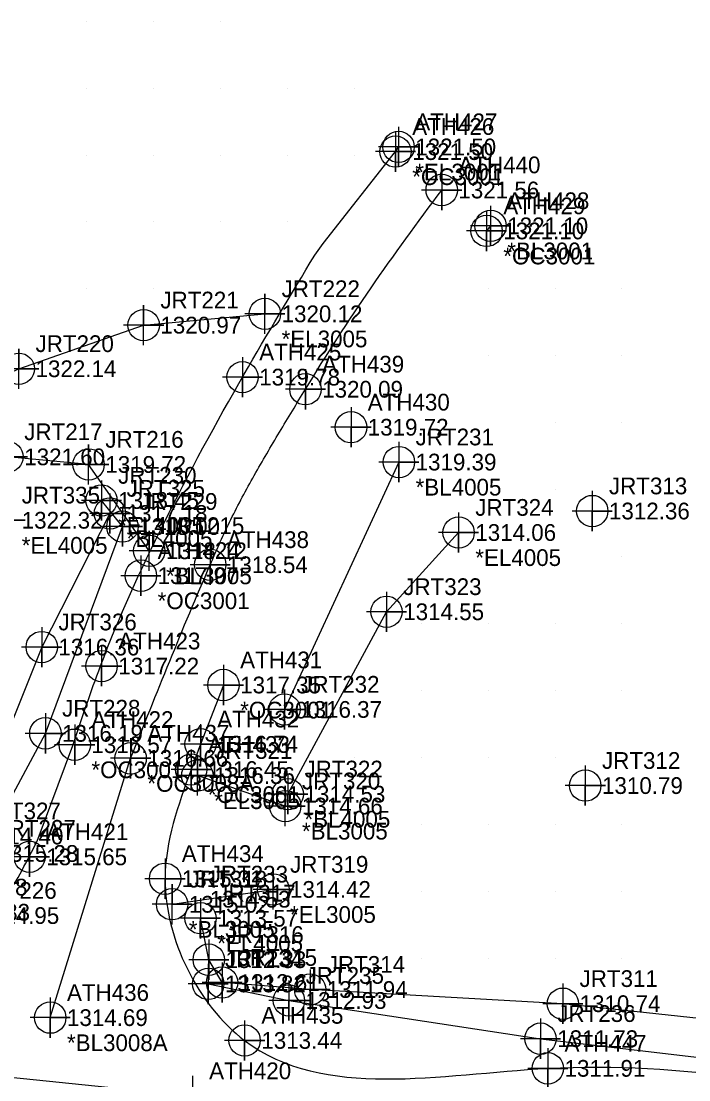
# Model space of a CAD drawing. Extents: x 1234484 to 1235382, y 695050 to 695510.
# Drawn here: x 1234580.2 to 1234680, y 695351.8 to 695510 of the extents above; entities that cross this region are included whole.
import ezdxf

# ---------------------------------------------------------------- set-up
doc = ezdxf.new("R2010")
doc.units = 0
for name, color, linetype in [('Exist DTM Breakline', 7, 'Continuous'), ('Exist DTM Breakline Cogo Comment', 7, 'Continuous'), ('Exist DTM Breakline Cogo Elevation', 7, 'Continuous'), ('Exist DTM Breakline Cogo Number', 7, 'Continuous'), ('Exist DTM Breakline Cogo Point CELL', 7, 'Continuous'), ('Exist DTM Crownline', 7, 'Continuous'), ('Exist DTM Crownline Cogo Comment', 7, 'Continuous'), ('Exist DTM Crownline Cogo Elevation', 7, 'Continuous'), ('Exist DTM Crownline Cogo Number', 7, 'Continuous'), ('Exist DTM Crownline Cogo Point CELL', 7, 'Continuous'), ('Exist DTM QL2 LIDAR Elevation Point', 7, 'Continuous'), ('Exist DTM Regular Point CELL', 7, 'Continuous'), ('Exist DTM Regular Point Cogo Elevation', 7, 'Continuous'), ('Exist DTM Regular Point Cogo Number', 7, 'Continuous'), ('Exist Roads EOP', 7, 'Continuous'), ('Exist Roads EOP Cogo Comment', 7, 'Continuous'), ('Exist Roads EOP Cogo Elevation', 7, 'Continuous'), ('Exist Roads EOP Cogo Number', 7, 'Continuous'), ('Exist Roads EOP Cogo Point CELL', 7, 'Continuous'), ('Exist Roads Soil', 7, 'Continuous'), ('Exist Roads Soil Cogo Comment', 7, 'Continuous'), ('Exist Roads Soil Cogo Elevation', 7, 'Continuous'), ('Exist Roads Soil Cogo Number', 7, 'Continuous'), ('Exist Roads Soil Cogo Point CELL', 7, 'Continuous')]:
    doc.layers.add(name, color=color, linetype=linetype)

msp = doc.modelspace()

# ---------------------------------------------------------------- linework, layer by layer
at = {"layer": 'Exist DTM Breakline'}
for points in [[(1234636.655, 695444.117), (1234619.55, 695407.153)], [(1234512.96, 695371.423), (1234547.569, 695368.537), (1234564.304, 695370.629), (1234571.291, 695376.351), (1234574.148, 695385.63), (1234583.803, 695403.581), (1234595.326, 695434.478), (1234592.189, 695438.384)], [(1234593.455, 695436.439), (1234583.26, 695416.47), (1234571.92, 695388.234), (1234566.927, 695376.85), (1234557.842, 695374.246), (1234516.908, 695379.248)], [(1234620.043, 695394.492), (1234634.807, 695421.746), (1234645.575, 695433.589)], [(1234866.911, 695345.376), (1234823.763, 695348.478), (1234767.785, 695355.619), (1234719.498, 695356.897), (1234661.167, 695363.182), (1234623.376, 695365.3), (1234610.221, 695366.341), (1234608.231, 695369.759), (1234607.001, 695375.947)], [(1234608.156, 695366.132), (1234620.219, 695363.657), (1234657.83, 695357.954), (1234716.822, 695351.015), (1234771.134, 695347.284), (1234823.515, 695343.018), (1234867.598, 695341.251), (1234907.686, 695335.753), (1234932.171, 695332.602)]]:
    msp.add_lwpolyline(points, dxfattribs=at)
at = {"layer": 'Exist DTM Breakline Cogo Point CELL'}
for points in [[(1234636.655, 695447.117), (1234636.655, 695441.117), (1234636.655, 695444.117), (1234639.655, 695444.117), (1234633.655, 695444.117)], [(1234592.189, 695441.384), (1234592.189, 695435.384), (1234592.189, 695438.384), (1234595.189, 695438.384), (1234589.189, 695438.384)], [(1234577.768, 695438.42), (1234577.768, 695432.42), (1234577.768, 695435.42), (1234580.768, 695435.42), (1234574.768, 695435.42)], [(1234593.455, 695439.439), (1234593.455, 695433.439), (1234593.455, 695436.439), (1234596.455, 695436.439), (1234590.455, 695436.439)], [(1234595.326, 695437.478), (1234595.326, 695431.478), (1234595.326, 695434.478), (1234598.326, 695434.478), (1234592.326, 695434.478)], [(1234645.575, 695436.589), (1234645.575, 695430.589), (1234645.575, 695433.589), (1234648.575, 695433.589), (1234642.575, 695433.589)], [(1234634.807, 695424.746), (1234634.807, 695418.746), (1234634.807, 695421.746), (1234637.807, 695421.746), (1234631.807, 695421.746)], [(1234583.26, 695419.47), (1234583.26, 695413.47), (1234583.26, 695416.47), (1234586.26, 695416.47), (1234580.26, 695416.47)], [(1234619.55, 695410.153), (1234619.55, 695404.153), (1234619.55, 695407.153), (1234622.55, 695407.153), (1234616.55, 695407.153)], [(1234583.803, 695406.581), (1234583.803, 695400.581), (1234583.803, 695403.581), (1234586.803, 695403.581), (1234580.803, 695403.581)], [(1234620.043, 695397.492), (1234620.043, 695391.492), (1234620.043, 695394.492), (1234623.043, 695394.492), (1234617.043, 695394.492)], [(1234607.001, 695378.947), (1234607.001, 695372.947), (1234607.001, 695375.947), (1234610.001, 695375.947), (1234604.001, 695375.947)], [(1234608.231, 695372.759), (1234608.231, 695366.759), (1234608.231, 695369.759), (1234611.231, 695369.759), (1234605.231, 695369.759)], [(1234608.156, 695369.132), (1234608.156, 695363.132), (1234608.156, 695366.132), (1234611.156, 695366.132), (1234605.156, 695366.132)], [(1234610.221, 695369.341), (1234610.221, 695363.341), (1234610.221, 695366.341), (1234613.221, 695366.341), (1234607.221, 695366.341)], [(1234623.376, 695368.3), (1234623.376, 695362.3), (1234623.376, 695365.3), (1234626.376, 695365.3), (1234620.376, 695365.3)], [(1234620.219, 695366.657), (1234620.219, 695360.657), (1234620.219, 695363.657), (1234623.219, 695363.657), (1234617.219, 695363.657)], [(1234661.167, 695366.182), (1234661.167, 695360.182), (1234661.167, 695363.182), (1234664.167, 695363.182), (1234658.167, 695363.182)], [(1234657.83, 695360.954), (1234657.83, 695354.954), (1234657.83, 695357.954), (1234660.83, 695357.954), (1234654.83, 695357.954)]]:
    msp.add_lwpolyline(points, dxfattribs=at)
for centre in [(1234636.655, 695444.117), (1234592.189, 695438.384), (1234593.455, 695436.439), (1234595.326, 695434.478), (1234645.575, 695433.589), (1234634.807, 695421.746), (1234583.26, 695416.47), (1234619.55, 695407.153), (1234583.803, 695403.581), (1234620.043, 695394.492), (1234607.001, 695375.947), (1234608.231, 695369.759), (1234608.156, 695366.132), (1234610.221, 695366.341), (1234623.376, 695365.3), (1234620.219, 695363.657), (1234661.167, 695363.182), (1234657.83, 695357.954)]:
    msp.add_circle(centre, 2.344, dxfattribs=at)
at = {"layer": 'Exist DTM Crownline'}
msp.add_line((1234584.535, 695361.097), (1234596.552, 695399.846), dxfattribs=at)
msp.add_lwpolyline([(1234511.603, 695359.057), (1234605.73, 695349.422), (1234657.657, 695344.297), (1234715.146, 695339.445), (1234769.335, 695334.825), (1234822.546, 695330.321), (1234845.176, 695328.304), (1234903.738, 695322.57)], dxfattribs=at)
msp.add_spline([(1234596.552, 695399.846), (1234608.45, 695428.774), (1234611.54, 695435.549), (1234615.04, 695442.13), (1234618.803, 695448.589), (1234620.737, 695451.794), (1234622.682, 695454.995), (1234632.484, 695470.133), (1234643.051, 695484.772)], degree=3, dxfattribs=at)
at = {"layer": 'Exist DTM Crownline Cogo Point CELL'}
for points in [[(1234643.051, 695487.772), (1234643.051, 695481.772), (1234643.051, 695484.772), (1234646.051, 695484.772), (1234640.051, 695484.772)], [(1234622.682, 695457.995), (1234622.682, 695451.995), (1234622.682, 695454.995), (1234625.682, 695454.995), (1234619.682, 695454.995)], [(1234608.45, 695431.774), (1234608.45, 695425.774), (1234608.45, 695428.774), (1234611.45, 695428.774), (1234605.45, 695428.774)], [(1234596.552, 695402.846), (1234596.552, 695396.846), (1234596.552, 695399.846), (1234599.552, 695399.846), (1234593.552, 695399.846)], [(1234584.535, 695364.097), (1234584.535, 695358.097), (1234584.535, 695361.097), (1234587.535, 695361.097), (1234581.535, 695361.097)], [(1234605.787, 695352.401), (1234605.787, 695346.401), (1234605.787, 695349.401), (1234608.787, 695349.401), (1234602.787, 695349.401)]]:
    msp.add_lwpolyline(points, dxfattribs=at)
for centre in [(1234643.051, 695484.772), (1234622.682, 695454.995), (1234608.45, 695428.774), (1234596.552, 695399.846), (1234584.535, 695361.097)]:
    msp.add_circle(centre, 2.344, dxfattribs=at)
at = {"layer": 'Exist DTM QL2 LIDAR Elevation Point'}
for p, q in [((1234590, 695510), (1234590, 695510)), ((1234600, 695510), (1234600, 695510)), ((1234610, 695510), (1234610, 695510)), ((1234590, 695500), (1234590, 695500)), ((1234600, 695500), (1234600, 695500)), ((1234610, 695500), (1234610, 695500)), ((1234620, 695500), (1234620, 695500)), ((1234630, 695500), (1234630, 695500)), ((1234590, 695490), (1234590, 695490)), ((1234600, 695490), (1234600, 695490)), ((1234610, 695490), (1234610, 695490)), ((1234620, 695490), (1234620, 695490)), ((1234630, 695490), (1234630, 695490)), ((1234590, 695480), (1234590, 695480)), ((1234600, 695480), (1234600, 695480)), ((1234610, 695480), (1234610, 695480)), ((1234620, 695480), (1234620, 695480)), ((1234590, 695470), (1234590, 695470)), ((1234600, 695470), (1234600, 695470)), ((1234650, 695470), (1234650, 695470)), ((1234660, 695470), (1234660, 695470)), ((1234670, 695470), (1234670, 695470)), ((1234650, 695460), (1234650, 695460)), ((1234660, 695460), (1234660, 695460)), ((1234670, 695460), (1234670, 695460)), ((1234660, 695450), (1234660, 695450)), ((1234670, 695450), (1234670, 695450)), ((1234660, 695440), (1234660, 695440)), ((1234670, 695440), (1234670, 695440)), ((1234660, 695430), (1234660, 695430)), ((1234670, 695430), (1234670, 695430)), ((1234640, 695420), (1234640, 695420)), ((1234650, 695420), (1234650, 695420)), ((1234660, 695420), (1234660, 695420)), ((1234670, 695420), (1234670, 695420)), ((1234640, 695410), (1234640, 695410)), ((1234650, 695410), (1234650, 695410)), ((1234660, 695410), (1234660, 695410)), ((1234670, 695410), (1234670, 695410)), ((1234630, 695400), (1234630, 695400)), ((1234640, 695400), (1234640, 695400)), ((1234650, 695400), (1234650, 695400)), ((1234660, 695400), (1234660, 695400)), ((1234670, 695400), (1234670, 695400)), ((1234630, 695390), (1234630, 695390)), ((1234640, 695390), (1234640, 695390)), ((1234650, 695390), (1234650, 695390)), ((1234660, 695390), (1234660, 695390)), ((1234670, 695390), (1234670, 695390)), ((1234630, 695380), (1234630, 695380)), ((1234640, 695380), (1234640, 695380)), ((1234650, 695380), (1234650, 695380)), ((1234660, 695380), (1234660, 695380)), ((1234670, 695380), (1234670, 695380)), ((1234630, 695370), (1234630, 695370)), ((1234640, 695370), (1234640, 695370)), ((1234650, 695370), (1234650, 695370)), ((1234660, 695370), (1234660, 695370)), ((1234670, 695370), (1234670, 695370))]:
    msp.add_line(p, q, dxfattribs=at)
at = {"layer": 'Exist DTM Regular Point CELL'}
for points in [[(1234665.558, 695439.801), (1234665.558, 695433.801), (1234665.558, 695436.801), (1234668.558, 695436.801), (1234662.558, 695436.801)], [(1234664.52, 695398.773), (1234664.52, 695392.773), (1234664.52, 695395.773), (1234667.52, 695395.773), (1234661.52, 695395.773)]]:
    msp.add_lwpolyline(points, dxfattribs=at)
for centre in [(1234665.558, 695436.801), (1234664.52, 695395.773)]:
    msp.add_circle(centre, 2.344, dxfattribs=at)
at = {"layer": 'Exist Roads EOP'}
for p, q in [((1234650.362, 695479.414), (1234649.764, 695478.654)), ((1234624.08, 695475.04), (1234625.321, 695476.801)), ((1234610.424, 695410.802), (1234606.996, 695401.967)), ((1234582.557, 695387.479), (1234587.891, 695401.779)), ((1234606.996, 695401.967), (1234605.599, 695398.165))]:
    msp.add_line(p, q, dxfattribs=at)
msp.add_lwpolyline([(1234625.321, 695476.801), (1234636.15, 695490.511), (1234636.603, 695491.204)], dxfattribs=at)
for points in [[(1234587.891, 695401.779), (1234592.055, 695413.665), (1234601.543, 695435.06), (1234613.519, 695457.241), (1234624.08, 695475.04)], [(1234605.599, 695398.165), (1234601.696, 695381.855), (1234613.593, 695357.692), (1234658.916, 695353.52), (1234716.264, 695348.291), (1234770.499, 695343.743), (1234823.09, 695339.258), (1234845.762, 695337.371), (1234903.754, 695331.785), (1234928.613, 695329.389)], [(1234548.726, 695364.834), (1234560.064, 695366.444), (1234570.143, 695371), (1234577.785, 695378.932), (1234582.557, 695387.479)]]:
    msp.add_spline(points, degree=3, dxfattribs=at)
at = {"layer": 'Exist Roads EOP Cogo Point CELL'}
for points in [[(1234636.15, 695493.511), (1234636.15, 695487.511), (1234636.15, 695490.511), (1234639.15, 695490.511), (1234633.15, 695490.511)], [(1234636.603, 695494.204), (1234636.603, 695488.204), (1234636.603, 695491.204), (1234639.603, 695491.204), (1234633.603, 695491.204)], [(1234650.362, 695482.414), (1234650.362, 695476.414), (1234650.362, 695479.414), (1234653.362, 695479.414), (1234647.362, 695479.414)], [(1234649.764, 695481.654), (1234649.764, 695475.654), (1234649.764, 695478.654), (1234652.764, 695478.654), (1234646.764, 695478.654)], [(1234613.272, 695459.809), (1234613.272, 695453.809), (1234613.272, 695456.809), (1234616.272, 695456.809), (1234610.272, 695456.809)], [(1234629.495, 695452.322), (1234629.495, 695446.322), (1234629.495, 695449.322), (1234632.495, 695449.322), (1234626.495, 695449.322)], [(1234598.088, 695430.141), (1234598.088, 695424.141), (1234598.088, 695427.141), (1234601.088, 695427.141), (1234595.088, 695427.141)], [(1234592.211, 695416.63), (1234592.211, 695410.63), (1234592.211, 695413.63), (1234595.211, 695413.63), (1234589.211, 695413.63)], [(1234610.424, 695413.802), (1234610.424, 695407.802), (1234610.424, 695410.802), (1234613.424, 695410.802), (1234607.424, 695410.802)], [(1234588.189, 695404.885), (1234588.189, 695398.885), (1234588.189, 695401.885), (1234591.189, 695401.885), (1234585.189, 695401.885)], [(1234606.996, 695404.967), (1234606.996, 695398.967), (1234606.996, 695401.967), (1234609.996, 695401.967), (1234603.996, 695401.967)], [(1234605.599, 695401.165), (1234605.599, 695395.165), (1234605.599, 695398.165), (1234608.599, 695398.165), (1234602.599, 695398.165)], [(1234581.437, 695388.123), (1234581.437, 695382.123), (1234581.437, 695385.123), (1234584.437, 695385.123), (1234578.437, 695385.123)], [(1234601.696, 695384.855), (1234601.696, 695378.855), (1234601.696, 695381.855), (1234604.696, 695381.855), (1234598.696, 695381.855)], [(1234613.593, 695360.692), (1234613.593, 695354.692), (1234613.593, 695357.692), (1234616.593, 695357.692), (1234610.593, 695357.692)], [(1234658.916, 695356.52), (1234658.916, 695350.52), (1234658.916, 695353.52), (1234661.916, 695353.52), (1234655.916, 695353.52)]]:
    msp.add_lwpolyline(points, dxfattribs=at)
for centre in [(1234636.603, 695491.204), (1234636.15, 695490.511), (1234649.764, 695478.654), (1234650.362, 695479.414), (1234613.272, 695456.809), (1234629.495, 695449.322), (1234598.088, 695427.141), (1234592.211, 695413.63), (1234610.424, 695410.802), (1234588.189, 695401.885), (1234606.996, 695401.967), (1234605.599, 695398.165), (1234581.437, 695385.123), (1234601.696, 695381.855), (1234613.593, 695357.692), (1234658.916, 695353.52)]:
    msp.add_circle(centre, 2.344, dxfattribs=at)
at = {"layer": 'Exist Roads Soil'}
for p, q in [((1234619.664, 695392.714), (1234606.525, 695397.271)), ((1234602.747, 695378.036), (1234617.883, 695380.258))]:
    msp.add_line(p, q, dxfattribs=at)
for points in [[(1234561.501, 695449.917), (1234579.837, 695458.059), (1234598.499, 695464.576), (1234616.621, 695466.265)], [(1234599.338, 695430.861), (1234590.269, 695443.761), (1234578.15, 695444.893), (1234563.39, 695438.311)]]:
    msp.add_lwpolyline(points, dxfattribs=at)
at = {"layer": 'Exist Roads Soil Cogo Point CELL'}
for points in [[(1234616.621, 695463.265), (1234616.621, 695469.265), (1234616.621, 695466.265), (1234619.621, 695466.265), (1234613.621, 695466.265)], [(1234598.499, 695461.576), (1234598.499, 695467.576), (1234598.499, 695464.576), (1234601.499, 695464.576), (1234595.499, 695464.576)], [(1234579.837, 695455.059), (1234579.837, 695461.059), (1234579.837, 695458.059), (1234582.837, 695458.059), (1234576.837, 695458.059)], [(1234578.15, 695441.893), (1234578.15, 695447.893), (1234578.15, 695444.893), (1234581.15, 695444.893), (1234575.15, 695444.893)], [(1234590.269, 695440.761), (1234590.269, 695446.761), (1234590.269, 695443.761), (1234593.269, 695443.761), (1234587.269, 695443.761)], [(1234599.338, 695427.861), (1234599.338, 695433.861), (1234599.338, 695430.861), (1234602.338, 695430.861), (1234596.338, 695430.861)], [(1234606.525, 695394.271), (1234606.525, 695400.271), (1234606.525, 695397.271), (1234609.525, 695397.271), (1234603.525, 695397.271)], [(1234619.664, 695389.714), (1234619.664, 695395.714), (1234619.664, 695392.714), (1234622.664, 695392.714), (1234616.664, 695392.714)], [(1234617.883, 695377.258), (1234617.883, 695383.258), (1234617.883, 695380.258), (1234620.883, 695380.258), (1234614.883, 695380.258)], [(1234602.747, 695375.036), (1234602.747, 695381.036), (1234602.747, 695378.036), (1234605.747, 695378.036), (1234599.747, 695378.036)]]:
    msp.add_lwpolyline(points, dxfattribs=at)
for centre in [(1234616.621, 695466.265), (1234598.499, 695464.576), (1234579.837, 695458.059), (1234578.15, 695444.893), (1234590.269, 695443.761), (1234599.338, 695430.861), (1234606.525, 695397.271), (1234619.664, 695392.714), (1234617.883, 695380.258), (1234602.747, 695378.036)]:
    msp.add_circle(centre, 2.344, dxfattribs=at)

# ---------------------------------------------------------------- texts
at = {"layer": 'Exist DTM Breakline Cogo Comment'}
for s, p in [('*BL4005', (1234639.155, 695439.117)), ('*EL4005', (1234594.689, 695433.384)), ('*BL4005', (1234595.955, 695431.439)), ('*EL4005', (1234580.268, 695430.42)), ('*EL4005', (1234648.075, 695428.589)), ('*BL4005', (1234622.543, 695389.492)), ('*EL4005', (1234609.501, 695370.947))]:
    msp.add_text(s, height=2.5, dxfattribs=at).set_placement(p)
at = {"layer": 'Exist DTM Breakline Cogo Elevation'}
for s, p in [('1319.39', (1234639.155, 695442.867)), ('1318.45', (1234594.689, 695437.134)), ('1322.32', (1234580.268, 695434.17)), ('1317.18', (1234595.955, 695435.189)), ('1318.00', (1234597.826, 695433.228)), ('1314.06', (1234648.075, 695432.339)), ('1314.55', (1234637.307, 695420.496)), ('1316.36', (1234585.76, 695415.22)), ('1316.37', (1234622.05, 695405.903)), ('1316.19', (1234586.303, 695402.331)), ('1314.53', (1234622.543, 695393.242)), ('1314.40', (1234574.42, 695386.984)), ('1315.28', (1234576.648, 695384.38)), ('1314.53', (1234608.38, 695377.542)), ('1313.83', (1234569.427, 695375.6)), ('1314.95', (1234573.791, 695375.101)), ('1313.57', (1234609.501, 695374.697)), ('1312.33', (1234610.731, 695368.509)), ('1313.82', (1234610.656, 695364.882)), ('1312.61', (1234612.721, 695365.091)), ('1311.94', (1234625.876, 695364.05)), ('1312.93', (1234622.719, 695362.407)), ('1310.74', (1234663.667, 695361.932)), ('1311.73', (1234660.33, 695356.704))]:
    msp.add_text(s, height=2.5, dxfattribs=at).set_placement(p)
at = {"layer": 'Exist DTM Breakline Cogo Number'}
for s, p in [('JRT231', (1234639.155, 695446.617)), ('JRT230', (1234594.689, 695440.884)), ('JRT325', (1234595.955, 695438.939)), ('JRT335', (1234580.268, 695437.92)), ('JRT229', (1234597.826, 695436.978)), ('JRT324', (1234648.075, 695436.089)), ('JRT323', (1234637.307, 695424.246)), ('JRT326', (1234585.76, 695418.97)), ('JRT232', (1234622.05, 695409.653)), ('JRT228', (1234586.303, 695406.081)), ('JRT322', (1234622.543, 695396.992)), ('JRT327', (1234574.42, 695390.734)), ('JRT227', (1234576.648, 695388.13)), ('JRT233', (1234608.38, 695381.292)), ('JRT328', (1234569.427, 695379.35)), ('JRT226', (1234573.791, 695378.851)), ('JRT317', (1234609.501, 695378.447)), ('JRT316', (1234610.731, 695372.259)), ('JRT234', (1234610.656, 695368.632)), ('JRT315', (1234612.721, 695368.841)), ('JRT314', (1234625.876, 695367.8)), ('JRT235', (1234622.719, 695366.157)), ('JRT311', (1234663.667, 695365.682)), ('JRT236', (1234660.33, 695360.454))]:
    msp.add_text(s, height=2.5, dxfattribs=at).set_placement(p)
at = {"layer": 'Exist DTM Crownline Cogo Comment'}
for s, p in [('*OC3008A', (1234599.052, 695394.846)), ('*BL3008A', (1234587.035, 695356.097))]:
    msp.add_text(s, height=2.5, dxfattribs=at).set_placement(p)
at = {"layer": 'Exist DTM Crownline Cogo Elevation'}
for s, p in [('1321.56', (1234645.551, 695483.522)), ('1320.09', (1234625.182, 695453.745)), ('1318.54', (1234610.95, 695427.524)), ('1316.66', (1234599.052, 695398.596)), ('1314.69', (1234587.035, 695359.847))]:
    msp.add_text(s, height=2.5, dxfattribs=at).set_placement(p)
at = {"layer": 'Exist DTM Crownline Cogo Number'}
for s, p in [('ATH440', (1234645.551, 695487.272)), ('ATH439', (1234625.182, 695457.495)), ('ATH438', (1234610.95, 695431.274)), ('ATH437', (1234599.052, 695402.346)), ('ATH436', (1234587.035, 695363.597)), ('ATH420', (1234608.287, 695351.901))]:
    msp.add_text(s, height=2.5, dxfattribs=at).set_placement(p)
at = {"layer": 'Exist DTM Regular Point Cogo Elevation'}
for s, p in [('1312.36', (1234668.058, 695435.551)), ('1310.79', (1234667.02, 695394.523))]:
    msp.add_text(s, height=2.5, dxfattribs=at).set_placement(p)
at = {"layer": 'Exist DTM Regular Point Cogo Number'}
for s, p in [('JRT313', (1234668.058, 695439.301)), ('JRT312', (1234667.02, 695398.273))]:
    msp.add_text(s, height=2.5, dxfattribs=at).set_placement(p)
at = {"layer": 'Exist Roads EOP Cogo Comment'}
for s, p in [('*EL3001', (1234639.103, 695486.204)), ('*OC3001', (1234638.65, 695485.511)), ('*OC3001', (1234652.264, 695473.654)), ('*BL3001', (1234652.862, 695474.414)), ('*OC3001', (1234600.588, 695422.141)), ('*OC3001', (1234612.924, 695405.802)), ('*OC3001', (1234590.689, 695396.885)), ('*OC3001', (1234608.099, 695393.165))]:
    msp.add_text(s, height=2.5, dxfattribs=at).set_placement(p)
at = {"layer": 'Exist Roads EOP Cogo Elevation'}
for s, p in [('1321.50', (1234638.65, 695489.261)), ('1321.50', (1234639.103, 695489.954)), ('1321.10', (1234652.862, 695478.164)), ('1321.10', (1234652.264, 695477.404)), ('1319.78', (1234615.772, 695455.559)), ('1319.72', (1234631.995, 695448.072)), ('1317.97', (1234600.588, 695425.891)), ('1317.22', (1234594.711, 695412.38)), ('1317.35', (1234612.924, 695409.552)), ('1316.57', (1234590.689, 695400.635)), ('1316.74', (1234609.496, 695400.717)), ('1316.45', (1234608.099, 695396.915)), ('1315.65', (1234583.937, 695383.873)), ('1315.31', (1234604.196, 695380.605)), ('1313.44', (1234616.093, 695356.442)), ('1311.91', (1234661.416, 695352.27))]:
    msp.add_text(s, height=2.5, dxfattribs=at).set_placement(p)
at = {"layer": 'Exist Roads EOP Cogo Number'}
for s, p in [('ATH426', (1234638.65, 695493.011)), ('ATH427', (1234639.103, 695493.704)), ('ATH428', (1234652.862, 695481.914)), ('ATH429', (1234652.264, 695481.154)), ('ATH425', (1234615.772, 695459.309)), ('ATH430', (1234631.995, 695451.822)), ('ATH424', (1234600.588, 695429.641)), ('ATH423', (1234594.711, 695416.13)), ('ATH431', (1234612.924, 695413.302)), ('ATH422', (1234590.689, 695404.385)), ('ATH432', (1234609.496, 695404.467)), ('ATH433', (1234608.099, 695400.665)), ('ATH421', (1234583.937, 695387.623)), ('ATH434', (1234604.196, 695384.355)), ('ATH435', (1234616.093, 695360.192)), ('ATH447', (1234661.416, 695356.02))]:
    msp.add_text(s, height=2.5, dxfattribs=at).set_placement(p)
at = {"layer": 'Exist Roads Soil Cogo Comment'}
for s, p in [('*EL3005', (1234619.121, 695461.265)), ('*BL3005', (1234601.838, 695425.861)), ('*EL3005', (1234609.025, 695392.271)), ('*BL3005', (1234622.164, 695387.714)), ('*EL3005', (1234620.383, 695375.258)), ('*BL3005', (1234605.247, 695373.036))]:
    msp.add_text(s, height=2.5, dxfattribs=at).set_placement(p)
at = {"layer": 'Exist Roads Soil Cogo Elevation'}
for s, p in [('1320.12', (1234619.121, 695465.015)), ('1320.97', (1234600.999, 695463.326)), ('1322.14', (1234582.337, 695456.809)), ('1321.60', (1234580.65, 695443.643)), ('1319.72', (1234592.769, 695442.511)), ('1318.12', (1234601.838, 695429.611)), ('1316.36', (1234609.025, 695396.021)), ('1314.66', (1234622.164, 695391.464)), ('1314.42', (1234620.383, 695379.008)), ('1315.02', (1234605.247, 695376.786))]:
    msp.add_text(s, height=2.5, dxfattribs=at).set_placement(p)
at = {"layer": 'Exist Roads Soil Cogo Number'}
for s, p in [('JRT222', (1234619.121, 695468.765)), ('JRT221', (1234600.999, 695467.076)), ('JRT220', (1234582.337, 695460.559)), ('JRT217', (1234580.65, 695447.393)), ('JRT216', (1234592.769, 695446.261)), ('JRT215', (1234601.838, 695433.361)), ('JRT321', (1234609.025, 695399.771)), ('JRT320', (1234622.164, 695395.214)), ('JRT319', (1234620.383, 695382.758)), ('JRT318', (1234605.247, 695380.536))]:
    msp.add_text(s, height=2.5, dxfattribs=at).set_placement(p)

doc.saveas('drawing.dxf')
